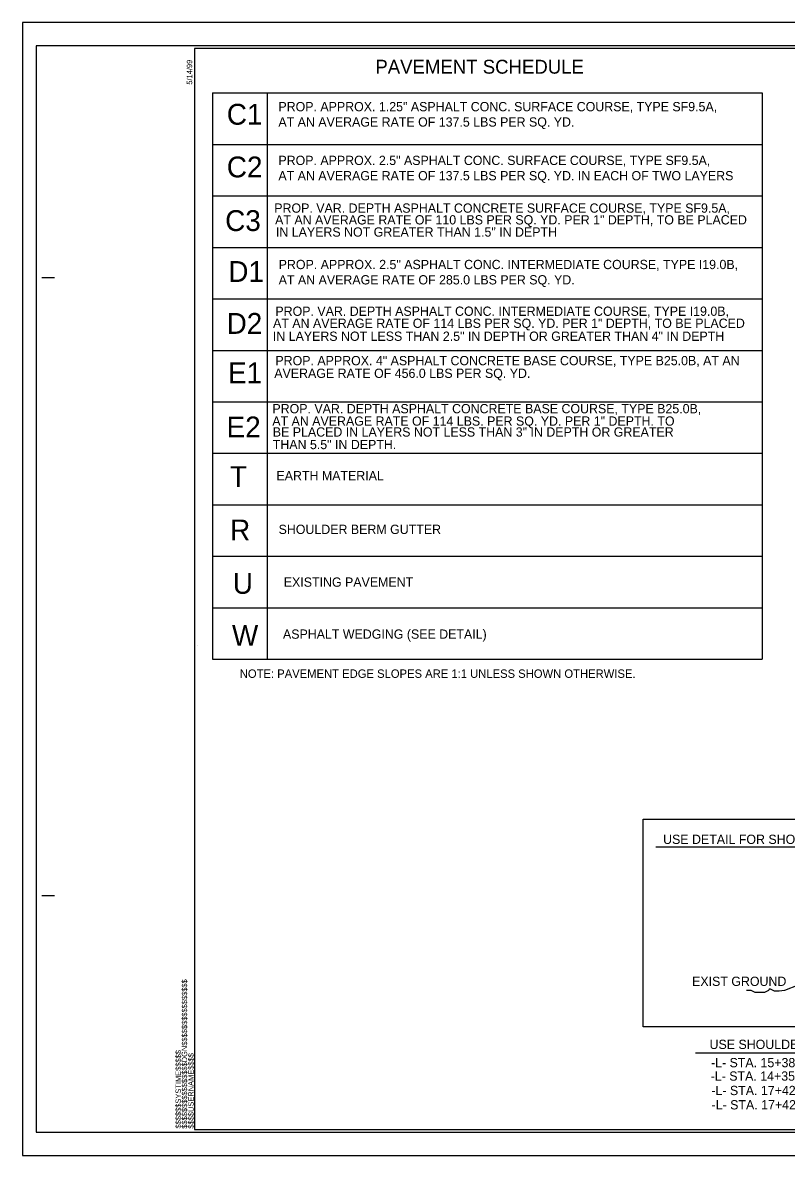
# Model space of a CAD drawing. Extents: x 193555 to 203883, y 190245 to 194645.
# Drawn here: x 193555 to 196523, y 190245 to 194645 of the extents above; entities that cross this region are included whole.
import ezdxf

# ---------------------------------------------------------------- set-up
doc = ezdxf.new("R2010")
doc.units = 0
for name, color, linetype in [('Old_Level_1', 7, 'Continuous'), ('Old_Level_18', 7, 'Continuous'), ('Old_Level_21', 7, 'Continuous'), ('Old_Level_41', 7, 'Continuous'), ('Old_Level_46', 7, 'Continuous'), ('Old_Level_50', 7, 'Continuous'), ('Old_Level_51', 7, 'Continuous'), ('Old_Level_52', 7, 'Continuous'), ('Typical Slope Point Local CELL', 7, 'Continuous')]:
    doc.layers.add(name, color=color, linetype=linetype)

msp = doc.modelspace()

# ---------------------------------------------------------------- linework, layer by layer
at = {"layer": 'Old_Level_1'}
for p, q in [((194292.9, 194371.9), (194292.9, 192171.9)), ((194292.9, 194371.9), (196429.5, 194371.9)), ((194504.8, 194371.9), (194504.8, 192171.9)), ((196429.5, 194371.9), (196429.5, 192171.9)), ((194292.9, 194171.9), (196429.5, 194171.9)), ((194292.9, 193971.9), (196429.5, 193971.9)), ((194292.9, 193771.9), (196429.5, 193771.9)), ((194292.9, 193571.9), (196429.5, 193571.9)), ((194292.9, 193371.9), (196429.5, 193371.9)), ((194292.9, 193171.9), (196429.5, 193171.9)), ((194292.9, 192971.9), (196429.5, 192971.9)), ((194292.9, 192971.9), (196429.5, 192971.9)), ((194292.9, 192771.9), (196429.5, 192771.9)), ((194292.9, 192571.9), (196429.5, 192571.9)), ((194292.9, 192371.9), (196429.5, 192371.9)), ((194235.8, 192223.6), (194235.8, 192223.6)), ((194292.9, 192171.9), (196429.5, 192171.9)), ((196015.5, 191443.7), (197082.9, 191443.7)), ((197014.3, 191083.5), (196516.2, 190884.9)), ((196169.9, 190642.8), (197237.4, 190642.8))]:
    msp.add_line(p, q, dxfattribs=at)
msp.add_lwpolyline([(195967.3, 191550.4), (197516.1, 191550.4), (197516.1, 190744), (195967.3, 190744)], close=True, dxfattribs=at)
at = {"layer": 'Old_Level_18'}
msp.add_lwpolyline([(200223.1, 194544.8), (194223.1, 194544.8), (194223.1, 190344.8), (200223.1, 190344.8)], close=True, dxfattribs=at)
at = {"layer": 'Old_Level_41'}
for p, q in [((193629.1, 193654.8), (193679.1, 193654.8)), ((193629.1, 191254.8), (193679.1, 191254.8))]:
    msp.add_line(p, q, dxfattribs=at)
at = {"layer": 'Old_Level_46'}
msp.add_line((194227.1, 194544.8), (194227.1, 194544.8), dxfattribs=at)
at = {"layer": 'Old_Level_50'}
msp.add_line((193555.1, 190244.8), (193555.1, 190244.8), dxfattribs=at)
msp.add_lwpolyline([(200273.1, 194555), (193607.1, 194555), (193607.1, 190334.6), (200273.1, 190334.6)], close=True, dxfattribs=at)
at = {"layer": 'Old_Level_51'}
msp.add_lwpolyline([(200291.1, 194644.8), (193555.1, 194644.8), (193555.1, 190244.8), (200291.1, 190244.8)], close=True, dxfattribs=at)
at = {"layer": 'Old_Level_52'}
msp.add_line((193607.1, 190334.6), (193607.1, 190334.6), dxfattribs=at)
at = {"layer": 'Typical Slope Point Local CELL'}
msp.add_lwpolyline([(196516.2, 190884.9), (196495.4, 190882.3), (196490.3, 190882.3), (196482.5, 190882.3), (196477.3, 190882.3), (196472.1, 190884.9), (196466.9, 190887.5), (196461.7, 190890.1), (196456.5, 190890.1), (196453.9, 190884.9), (196448.7, 190882.3), (196443.6, 190879.7), (196438.4, 190877.1), (196433.2, 190877.1), (196428, 190877.1), (196422.8, 190877.1), (196417.6, 190877.1), (196412.4, 190877.1), (196407.3, 190877.1), (196402.1, 190877.1), (196396.9, 190879.7), (196391.7, 190882.3), (196386.5, 190884.9), (196378.7, 190884.9), (196373.5, 190884.9), (196368.3, 190884.9)], dxfattribs=at)

# ---------------------------------------------------------------- texts
at = {"layer": 'Old_Level_1'}
for s, height, p in [('PAVEMENT SCHEDULE', 54, (194925.9, 194446.6)), ('C1', 81, (194348.6, 194248.4)), ('PROP. APPROX. 1.25" ASPHALT CONC. SURFACE COURSE, TYPE SF9.5A,', 36, (194549.1, 194300.6)), ('AT AN AVERAGE RATE OF 137.5 LBS PER SQ. YD.', 36, (194549.1, 194241)), ('PROP. APPROX. 2.5" ASPHALT CONC. SURFACE COURSE, TYPE SF9.5A,', 36, (194549.1, 194091.8)), ('C2', 81, (194348.6, 194043.7)), ('AT AN AVERAGE RATE OF 137.5 LBS PER SQ. YD. IN EACH OF TWO LAYERS', 36, (194549.1, 194032.3)), ('C3', 81, (194342.2, 193835.4)), ('PROP. VAR. DEPTH ASPHALT CONCRETE SURFACE COURSE, TYPE SF9.5A,', 36, (194533.1, 193906.5)), ('AT AN AVERAGE RATE OF 110 LBS PER SQ. YD. PER 1" DEPTH, TO BE PLACED ', 36, (194536.3, 193860.9)), ('IN LAYERS NOT GREATER THAN 1.5" IN DEPTH', 36, (194539.5, 193813.6)), ('D1', 81, (194354.4, 193637.7)), ('PROP. APPROX. 2.5" ASPHALT CONC. INTERMEDIATE COURSE, TYPE I19.0B,', 36, (194550.2, 193687.4)), ('AT AN AVERAGE RATE OF 285.0 LBS PER SQ. YD.', 36, (194550.2, 193627.9)), ('D2', 81, (194347.9, 193436)), ('PROP. VAR. DEPTH ASPHALT CONC. INTERMEDIATE COURSE, TYPE I19.0B,', 36, (194537.4, 193505.9)), ('AT AN AVERAGE RATE OF 114 LBS PER SQ. YD. PER 1" DEPTH, TO BE PLACED', 36, (194528.3, 193459.2)), ('IN LAYERS NOT LESS THAN 2.5" IN DEPTH OR GREATER THAN 4" IN DEPTH', 36, (194527.5, 193408.8)), ('PROP. APPROX. 4" ASPHALT CONCRETE BASE COURSE, TYPE B25.0B, AT AN', 36, (194537.4, 193314)), ('E1', 81, (194353.2, 193244.1)), ('AVERAGE RATE OF 456.0 LBS PER SQ. YD.', 36, (194533.1, 193264.8)), ('PROP. VAR. DEPTH ASPHALT CONCRETE BASE COURSE, TYPE B25.0B,', 36, (194525.8, 193127.4)), ('E2', 81, (194347.7, 193033.8)), ('AT AN AVERAGE RATE OF 114 LBS. PER SQ. YD. PER 1" DEPTH. TO', 36, (194525.4, 193079.2)), ('BE PLACED IN LAYERS NOT LESS THAN 3" IN DEPTH OR GREATER', 36, (194527.3, 193036.8)), ('THAN 5.5" IN DEPTH.', 36, (194527.3, 192988.1)), ('T', 81, (194360.5, 192840.9)), ('EARTH MATERIAL', 36, (194541.6, 192867)), ('R', 81, (194361.5, 192633.6)), ('SHOULDER BERM GUTTER', 36, (194549.9, 192658.6)), ('U', 81, (194371.8, 192426.2)), ('EXISTING PAVEMENT', 36, (194570, 192453.6)), ('W', 81, (194368.6, 192224.3)), ('ASPHALT WEDGING (SEE DETAIL)', 36, (194566.8, 192251.6)), ('USE DETAIL FOR SHOULDER BERM GUTTER', 36, (196044.2, 191454.5)), ('EXIST GROUND', 36, (196156.8, 190902.9)), ('USE SHOULDER BERM GUTTER', 36, (196224.7, 190657.9)), ('-L- STA. 15+38.00 TO 15+53.00 LT.', 36, (196230.2, 190587)), ('-L- STA. 14+35.00 TO 15+53.00 RT.', 36, (196229.1, 190534.8)), ('-L- STA. 17+42.00 TO 17+79.00 LT.', 36, (196231.7, 190478.8)), ('-L- STA. 17+42.00 TO 17+80.00 RT.', 36, (196232.6, 190423.2))]:
    msp.add_text(s, height=height, dxfattribs=at).set_placement(p)
at = {"layer": 'Old_Level_21'}
msp.add_text('NOTE: PAVEMENT EDGE SLOPES ARE 1:1 UNLESS SHOWN OTHERWISE.', height=32.65, dxfattribs=at).set_placement((194398.9, 192099.7))
at = {"layer": 'Old_Level_41'}
for s, p in [('5/14/99', (194214.1, 194404)), ('$$$$$$$$$$$$$$$$DGN$$$$$$$$$$$$$$$$', (194194.5, 190348.2)), ('$$$$$$SYSTIME$$$$$', (194170.3, 190349)), ('$$$$USERNAME$$$$', (194219.7, 190348.6))]:
    msp.add_text(s, height=21, rotation=90, dxfattribs=at).set_placement(p)

doc.saveas('drawing.dxf')
